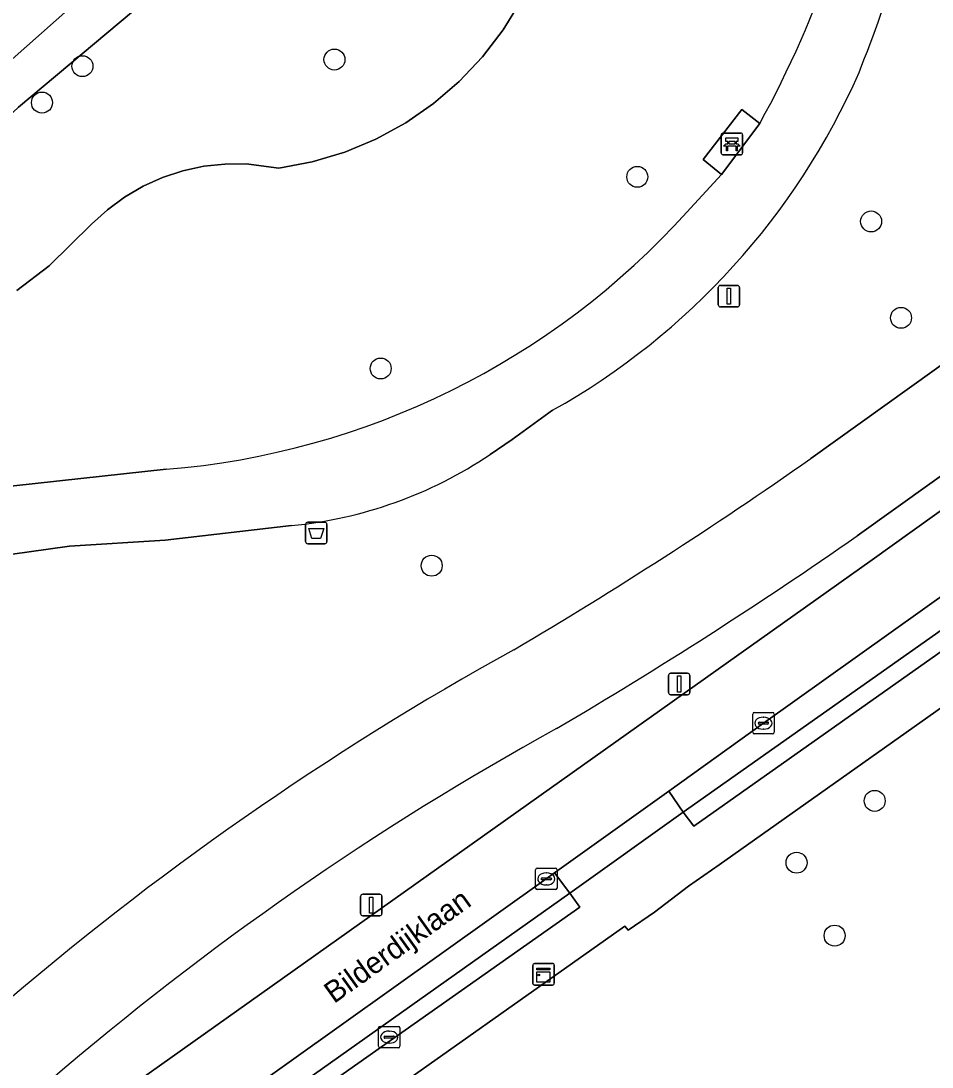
# Model space of a CAD drawing. Extents: x 161347 to 161881, y 382161 to 382804.
# Drawn here: x 161456.75 to 161499.19, y 382680.34 to 382729.09 of the extents above; entities that cross this region are included whole.
import ezdxf

# ---------------------------------------------------------------- set-up
doc = ezdxf.new("R2010")
doc.units = 0
for name, color, linetype in [('IMGEO_Afvalbak', 7, 'Continuous'), ('IMGEO_Bank', 7, 'Continuous'), ('IMGEO_Berm_groen', 7, 'Continuous'), ('IMGEO_Boom', 7, 'Continuous'), ('IMGEO_Erf', 7, 'Continuous'), ('IMGEO_Fietspad_gesloten', 7, 'Continuous'), ('IMGEO_Groenvoorziening', 7, 'Continuous'), ('IMGEO_Kast', 7, 'Continuous'), ('IMGEO_Kolk', 7, 'Continuous'), ('IMGEO_Lichtmast', 7, 'Continuous'), ('IMGEO_Oever', 7, 'Continuous'), ('IMGEO_Openbare_ruimte_label', 7, 'Continuous'), ('IMGEO_Rijbaan_lokaal_open', 7, 'Continuous'), ('IMGEO_Voetpad_gesloten', 7, 'Continuous'), ('IMGEO_Voetpad_open', 7, 'Continuous'), ('IMGEO_Waterloop', 7, 'Continuous')]:
    doc.layers.add(name, color=color, linetype=linetype)

msp = doc.modelspace()

# ---------------------------------------------------------------- linework, layer by layer
at = {"layer": 'IMGEO_Afvalbak'}
for p, q in [((161470.113, 382705.732), (161470.903, 382705.732)), ((161470.903, 382705.732), (161470.113, 382705.732)), ((161470.013, 382704.832), (161470.013, 382705.632)), ((161470.013, 382705.632), (161470.013, 382704.832)), ((161471.003, 382705.632), (161471.003, 382704.832)), ((161471.003, 382704.832), (161471.003, 382705.632)), ((161470.903, 382704.732), (161470.113, 382704.732)), ((161470.113, 382704.732), (161470.903, 382704.732))]:
    msp.add_line(p, q, dxfattribs=at)
msp.add_lwpolyline([(161470.156, 382705.446), (161470.86, 382705.446), (161470.711, 382704.976), (161470.305, 382704.976), (161470.156, 382705.446)], dxfattribs=at)
for centre, start, end in [((161470.113, 382705.632), 90, 180), ((161470.113, 382705.632), 90, 180), ((161470.903, 382705.632), 0, 90), ((161470.903, 382705.632), 360, 90), ((161470.113, 382704.832), 180, 270), ((161470.113, 382704.832), 180, 270), ((161470.903, 382704.832), 270, 0), ((161470.903, 382704.832), 270, 0)]:
    msp.add_arc(centre, 0.1, start, end, dxfattribs=at)
at = {"layer": 'IMGEO_Bank'}
for p, q in [((161489.37, 382722.935), (161489.37, 382723.776)), ((161489.37, 382723.776), (161489.37, 382722.935)), ((161489.445, 382723.86), (161490.286, 382723.86)), ((161490.286, 382723.86), (161489.445, 382723.86)), ((161490.37, 382723.785), (161490.37, 382722.944)), ((161490.37, 382722.944), (161490.37, 382723.785)), ((161489.679, 382723.366), (161489.679, 382723.472)), ((161489.723, 382723.472), (161489.723, 382723.366)), ((161490.011, 382723.478), (161489.729, 382723.478)), ((161489.729, 382723.36), (161490.011, 382723.36)), ((161490.017, 382723.366), (161490.017, 382723.472)), ((161490.061, 382723.472), (161490.061, 382723.366)), ((161490.295, 382722.86), (161489.454, 382722.86)), ((161489.454, 382722.86), (161490.295, 382722.86)), ((161490.067, 382723.258), (161489.674, 382723.258))]:
    msp.add_line(p, q, dxfattribs=at)
for points in [[(161489.617, 382723.258), (161489.475, 382723.258), (161489.587, 382723.36), (161489.673, 382723.36)], [(161489.673, 382723.478), (161489.587, 382723.478), (161489.587, 382723.639), (161490.15, 382723.639), (161490.15, 382723.478), (161490.067, 382723.478)], [(161490.067, 382723.36), (161490.15, 382723.36), (161490.262, 382723.258), (161490.123, 382723.258)], [(161489.667, 382723.251), (161489.667, 382723.044), (161489.624, 382723.044), (161489.624, 382723.251)], [(161490.117, 382723.251), (161490.117, 382723.044), (161490.073, 382723.044), (161490.073, 382723.251)]]:
    msp.add_lwpolyline(points, dxfattribs=at)
for centre, radius, start, end in [((161489.448, 382723.782), 0.0779, 92.4484, 184.2845), ((161489.448, 382723.782), 0.0779, 92.4484, 184.2845), ((161490.292, 382723.782), 0.0779, 2.4484, 94.2845), ((161490.292, 382723.782), 0.0779, 2.4484, 94.2845), ((161489.672, 382723.471), 0.00671, 2.8957, 87.1043), ((161489.672, 382723.367), 0.00671, 272.8957, 357.1043), ((161489.729, 382723.471), 0.00671, 92.8957, 177.1043), ((161489.729, 382723.367), 0.00671, 182.8957, 267.1043), ((161490.011, 382723.471), 0.00671, 2.8957, 87.1043), ((161490.011, 382723.367), 0.00671, 272.8957, 357.1043), ((161490.068, 382723.471), 0.00671, 92.8957, 177.1043), ((161490.068, 382723.367), 0.00671, 182.8957, 267.1043), ((161489.448, 382722.938), 0.0779, 182.4484, 274.2845), ((161489.448, 382722.938), 0.0779, 182.4484, 274.2845), ((161489.617, 382723.251), 0.00671, 2.8957, 87.1043), ((161489.674, 382723.251), 0.00671, 92.8957, 177.1043), ((161490.066, 382723.251), 0.00671, 2.8957, 87.1043), ((161490.123, 382723.251), 0.00671, 92.8957, 177.1043), ((161490.292, 382722.938), 0.0779, 272.4484, 4.2845), ((161490.292, 382722.938), 0.0779, 272.4484, 4.2845)]:
    msp.add_arc(centre, radius, start, end, dxfattribs=at)
at = {"layer": 'IMGEO_Berm_groen'}
for points in [[(161496.406, 382703.987), (161520.561, 382721.294), (161534.16, 382731.042), (161532.366, 382733.661), (161532.246, 382733.831)], [(161519.837, 382722.372), (161495.711, 382705.094)], [(161458.111, 382679.715), (161459.5, 382677.759), (161461.177, 382678.951), (161496.406, 382703.987)]]:
    msp.add_lwpolyline(points, dxfattribs=at)
for points in [[(161537.789, 382727.63), (161537.522, 382728.039), (161536.889, 382728.907), (161530.645, 382724.485), (161516.475, 382714.369), (161503.123, 382704.778), (161491.34, 382696.368), (161486.926, 382693.195), (161487.602, 382692.215)], [(161482.326, 382688.441), (161481.611, 382689.399), (161481.225, 382689.112), (161464.586, 382677.241), (161463.154, 382676.198), (161461.489, 382674.961), (161462.097, 382674.118)]]:
    msp.add_lwpolyline(points, close=True, dxfattribs=at)
for centre, radius, start, end in [((161369.649, 382886.421), 220.842, 300.49014, 304.80775), ((161548.88, 382574.336), 139.082, 118.88221, 130.74015)]:
    msp.add_arc(centre, radius, start, end, dxfattribs=at)
at = {"layer": 'IMGEO_Boom'}
for centre in [(161471.354, 382727.292), (161459.614, 382726.984), (161457.731, 382725.286), (161485.462, 382721.827), (161496.355, 382719.749), (161497.748, 382715.257), (161473.509, 382712.896), (161475.885, 382703.708), (161496.521, 382692.749), (161492.882, 382689.868), (161494.655, 382686.468)]:
    msp.add_circle(centre, 0.489, dxfattribs=at)
at = {"layer": 'IMGEO_Erf'}
msp.add_lwpolyline([(161539.475, 382725.265), (161539.023, 382724.966), (161500, 382697.359), (161489.273, 382689.77), (161487.851, 382688.777), (161486.262, 382687.566), (161485.031, 382686.717), (161484.889, 382686.908), (161471.792, 382677.655), (161467.896, 382674.919)], dxfattribs=at)
at = {"layer": 'IMGEO_Fietspad_gesloten'}
for points in [[(161523.309, 382730.357), (161521.173, 382728.603), (161519.215, 382727.108), (161518.831, 382726.815), (161493.541, 382708.697)], [(161495.711, 382705.094), (161519.837, 382722.372)]]:
    msp.add_lwpolyline(points, dxfattribs=at)
for centre, radius, start, end in [((161374.116, 382878.995), 207.999, 300.50782, 305.04089), ((161369.649, 382886.421), 220.842, 300.49014, 304.80775), ((161548.803, 382574.988), 142.653, 118.97036, 130.86988), ((161548.88, 382574.336), 139.082, 118.88221, 130.74015)]:
    msp.add_arc(centre, radius, start, end, dxfattribs=at)
at = {"layer": 'IMGEO_Groenvoorziening'}
for points in [[(161472.613, 382738.476), (161456.64, 382725.075)], [(161456.559, 382716.525), (161458.069, 382717.676), (161460.04, 382719.626), (161460.777, 382720.295), (161461.579, 382720.884), (161462.439, 382721.385), (161463.347, 382721.794), (161464.292, 382722.106), (161465.265, 382722.317), (161466.254, 382722.425), (161467.249, 382722.43), (161468.77, 382722.233), (161470.321, 382722.525), (161471.833, 382722.977), (161473.29, 382723.585), (161474.675, 382724.342), (161475.974, 382725.239), (161477.171, 382726.267), (161478.255, 382727.415), (161479.212, 382728.67), (161480.034, 382730.018)], [(161480.034, 382730.018), (161479.212, 382728.67), (161478.255, 382727.415), (161477.171, 382726.267), (161475.974, 382725.239), (161474.675, 382724.342), (161473.29, 382723.585), (161471.833, 382722.977), (161470.321, 382722.525), (161468.77, 382722.233), (161467.249, 382722.43), (161466.254, 382722.425), (161465.265, 382722.317), (161464.292, 382722.106), (161463.347, 382721.794), (161462.439, 382721.385), (161461.579, 382720.884), (161460.777, 382720.295), (161460.04, 382719.626), (161458.069, 382717.676), (161456.559, 382716.525)], [(161493.541, 382708.697), (161518.831, 382726.815)], [(161487.776, 382720.188), (161489.381, 382721.932), (161488.535, 382722.639), (161490.336, 382724.963), (161491.169, 382724.314)], [(161481.517, 382710.948), (161479.63, 382709.589), (161478.603, 382708.888)], [(161453.419, 382707.1), (161463.511, 382708.198)], [(161469.355, 382705.575), (161463.467, 382704.901), (161459.017, 382704.615), (161452.58, 382703.712), (161450.029, 382703.228), (161448.055, 382702.486), (161447.132, 382702.068), (161445.435, 382701.104), (161442.413, 382699.254), (161439.915, 382696.828), (161438.465, 382695.203), (161433.965, 382689.139), (161439.833, 382684.963), (161443.031, 382682.767), (161445.834, 382680.886)]]:
    msp.add_lwpolyline(points, dxfattribs=at)
for points in [[(161537.789, 382727.63), (161487.602, 382692.215), (161488.093, 382691.571), (161538.259, 382727.022)], [(161482.783, 382687.789), (161482.326, 382688.441), (161462.097, 382674.118), (161462.528, 382673.52)]]:
    msp.add_lwpolyline(points, close=True, dxfattribs=at)
for centre, radius, start, end in [((161447.83, 382748.107), 49.44, 331.2337, 351.2119), ((161426.836, 382754.189), 74.236, 338.25891, 347.08272), ((161465.125, 382740.155), 33.492, 299.3027, 336.2968), ((161460.556, 382744.728), 36.649, 274.6255, 317.965), ((161467.429, 382725.517), 20.034, 275.5179, 303.9012), ((161374.116, 382878.995), 207.999, 300.50782, 305.04089), ((161548.803, 382574.988), 142.653, 118.97036, 130.86988)]:
    msp.add_arc(centre, radius, start, end, dxfattribs=at)
at = {"layer": 'IMGEO_Kast'}
for p, q in [((161480.595, 382684.243), (161480.595, 382685.084)), ((161480.595, 382685.084), (161480.595, 382684.243)), ((161480.67, 382685.168), (161481.511, 382685.168)), ((161481.511, 382685.168), (161480.67, 382685.168)), ((161481.595, 382685.093), (161481.595, 382684.252)), ((161481.595, 382684.252), (161481.595, 382685.093)), ((161481.52, 382684.168), (161480.679, 382684.168)), ((161480.679, 382684.168), (161481.52, 382684.168))]:
    msp.add_line(p, q, dxfattribs=at)
for points in [[(161480.79, 382684.958), (161481.39, 382684.958), (161481.39, 382684.873), (161480.79, 382684.873), (161480.79, 382684.958)], [(161480.79, 382684.783), (161481.39, 382684.783), (161481.39, 382684.294), (161480.79, 382684.294), (161480.79, 382684.783)]]:
    msp.add_lwpolyline(points, dxfattribs=at)
msp.add_circle((161480.874, 382684.632), 0.0377, dxfattribs=at)
for centre, start, end in [((161480.673, 382685.09), 92.4484, 184.2845), ((161480.673, 382685.09), 92.4484, 184.2845), ((161481.517, 382685.09), 2.4484, 94.2845), ((161481.517, 382685.09), 2.4484, 94.2845), ((161480.673, 382684.246), 182.4484, 274.2845), ((161480.673, 382684.246), 182.4484, 274.2845), ((161481.517, 382684.246), 272.4484, 4.2845), ((161481.517, 382684.246), 272.4484, 4.2845)]:
    msp.add_arc(centre, 0.0779, start, end, dxfattribs=at)
at = {"layer": 'IMGEO_Kolk'}
for p, q in [((161490.839, 382695.942), (161490.839, 382696.794)), ((161490.914, 382696.868), (161491.766, 382696.868)), ((161491.327, 382696.648), (161491.352, 382696.648)), ((161491.84, 382696.794), (161491.84, 382695.942)), ((161491.098, 382696.362), (161491.098, 382696.374)), ((161491.536, 382696.325), (161491.138, 382696.325)), ((161491.141, 382696.411), (161491.539, 382696.411)), ((161491.35, 382696.088), (161491.325, 382696.088)), ((161491.582, 382696.374), (161491.582, 382696.362)), ((161491.766, 382695.868), (161490.914, 382695.868)), ((161480.724, 382688.686), (161480.724, 382689.538)), ((161480.799, 382689.612), (161481.651, 382689.612)), ((161481.026, 382689.155), (161481.424, 382689.155)), ((161481.212, 382689.392), (161481.237, 382689.392)), ((161481.725, 382689.538), (161481.725, 382688.686)), ((161480.983, 382689.106), (161480.983, 382689.118)), ((161481.421, 382689.069), (161481.023, 382689.069)), ((161481.235, 382688.832), (161481.21, 382688.832)), ((161481.467, 382689.118), (161481.467, 382689.106)), ((161481.651, 382688.612), (161480.799, 382688.612)), ((161473.406, 382681.313), (161473.406, 382682.165)), ((161473.481, 382682.239), (161474.333, 382682.239)), ((161473.894, 382682.019), (161473.919, 382682.019)), ((161474.407, 382682.165), (161474.407, 382681.313)), ((161473.665, 382681.733), (161473.665, 382681.745)), ((161474.103, 382681.696), (161473.705, 382681.696)), ((161473.708, 382681.782), (161474.106, 382681.782)), ((161473.917, 382681.459), (161473.892, 382681.459)), ((161474.149, 382681.745), (161474.149, 382681.733)), ((161474.333, 382681.239), (161473.481, 382681.239))]:
    msp.add_line(p, q, dxfattribs=at)
for points in [[(161490.839, 382695.942), (161490.839, 382696.794)], [(161490.914, 382696.868), (161491.766, 382696.868)], [(161491.84, 382696.794), (161491.84, 382695.942)], [(161491.766, 382695.868), (161490.914, 382695.868)], [(161480.724, 382688.686), (161480.724, 382689.538)], [(161480.799, 382689.612), (161481.651, 382689.612)], [(161481.725, 382689.538), (161481.725, 382688.686)], [(161481.651, 382688.612), (161480.799, 382688.612)], [(161473.406, 382681.313), (161473.406, 382682.165)], [(161473.481, 382682.239), (161474.333, 382682.239)], [(161474.407, 382682.165), (161474.407, 382681.313)], [(161474.333, 382681.239), (161473.481, 382681.239)]]:
    msp.add_lwpolyline(points, dxfattribs=at)
for centre, radius, start, end in [((161490.916, 382696.792), 0.0765, 91.552, 178.448), ((161490.916, 382696.792), 0.0765, 91.552, 178.448), ((161491.764, 382696.792), 0.0765, 1.552, 88.448), ((161491.764, 382696.792), 0.0765, 1.552, 88.448), ((161491.138, 382696.371), 0.0403, 85.8775, 175.7526), ((161491.135, 382696.361), 0.0366, 178.938, 274.7102), ((161491.539, 382696.368), 0.043, 264.8664, 352.4533), ((161491.543, 382696.373), 0.0386, 1.7309, 96.639), ((161490.916, 382695.944), 0.0765, 181.552, 268.448), ((161490.916, 382695.944), 0.0765, 181.552, 268.448), ((161491.764, 382695.944), 0.0765, 271.552, 358.448), ((161491.764, 382695.944), 0.0765, 271.552, 358.448), ((161480.801, 382689.536), 0.0765, 91.552, 178.448), ((161480.801, 382689.536), 0.0765, 91.552, 178.448), ((161481.023, 382689.115), 0.0403, 85.8775, 175.7526), ((161481.428, 382689.117), 0.0386, 1.7309, 96.639), ((161481.649, 382689.536), 0.0765, 1.552, 88.448), ((161481.649, 382689.536), 0.0765, 1.552, 88.448), ((161480.801, 382688.688), 0.0765, 181.552, 268.448), ((161480.801, 382688.688), 0.0765, 181.552, 268.448), ((161481.02, 382689.105), 0.0366, 178.938, 274.7102), ((161481.424, 382689.112), 0.043, 264.8664, 352.4533), ((161481.649, 382688.688), 0.0765, 271.552, 358.448), ((161481.649, 382688.688), 0.0765, 271.552, 358.448), ((161473.483, 382682.163), 0.0765, 91.552, 178.448), ((161473.483, 382682.163), 0.0765, 91.552, 178.448), ((161474.331, 382682.163), 0.0765, 1.552, 88.448), ((161474.331, 382682.163), 0.0765, 1.552, 88.448), ((161473.705, 382681.742), 0.0403, 85.8775, 175.7526), ((161473.702, 382681.732), 0.0366, 178.938, 274.7102), ((161474.106, 382681.739), 0.043, 264.8664, 352.4533), ((161474.11, 382681.744), 0.0386, 1.7309, 96.639), ((161473.483, 382681.315), 0.0765, 181.552, 268.448), ((161473.483, 382681.315), 0.0765, 181.552, 268.448), ((161474.331, 382681.315), 0.0765, 271.552, 358.448), ((161474.331, 382681.315), 0.0765, 271.552, 358.448)]:
    msp.add_arc(centre, radius, start, end, dxfattribs=at)
for centre, major_axis, ratio, start_param, end_param in [((161491.326, 382696.368), (-0.387, 0.002), 0.722429, 4.712389, 7.853982), ((161491.351, 382696.368), (-0.39, 0.002), 0.717154, 1.570796, 4.712389), ((161481.211, 382689.112), (-0.387, 0.002), 0.722429, 4.712389, 7.853982), ((161481.236, 382689.112), (-0.39, 0.002), 0.717154, 1.570796, 4.712389), ((161473.893, 382681.739), (-0.387, 0.002), 0.722429, 4.712389, 7.853982), ((161473.918, 382681.739), (-0.39, 0.002), 0.717154, 1.570796, 4.712389)]:
    msp.add_ellipse(centre, major_axis=major_axis, ratio=ratio, start_param=start_param, end_param=end_param, dxfattribs=at)
at = {"layer": 'IMGEO_Lichtmast'}
for p, q in [((161489.236, 382715.868), (161489.236, 382716.668)), ((161489.236, 382716.668), (161489.236, 382715.868)), ((161489.336, 382716.768), (161490.126, 382716.768)), ((161490.126, 382716.768), (161489.336, 382716.768)), ((161490.226, 382716.668), (161490.226, 382715.868)), ((161490.226, 382715.868), (161490.226, 382716.668)), ((161490.126, 382715.768), (161489.336, 382715.768)), ((161489.336, 382715.768), (161490.126, 382715.768)), ((161486.917, 382697.796), (161486.917, 382698.596)), ((161486.917, 382698.596), (161486.917, 382697.796)), ((161487.017, 382698.696), (161487.807, 382698.696)), ((161487.807, 382698.696), (161487.017, 382698.696)), ((161487.907, 382698.596), (161487.907, 382697.796)), ((161487.907, 382697.796), (161487.907, 382698.596)), ((161487.807, 382697.696), (161487.017, 382697.696)), ((161487.017, 382697.696), (161487.807, 382697.696)), ((161472.575, 382687.493), (161472.575, 382688.293)), ((161472.575, 382688.293), (161472.575, 382687.493)), ((161472.675, 382688.393), (161473.465, 382688.393)), ((161473.465, 382688.393), (161472.675, 382688.393)), ((161473.565, 382688.293), (161473.565, 382687.493)), ((161473.565, 382687.493), (161473.565, 382688.293)), ((161473.465, 382687.393), (161472.675, 382687.393)), ((161472.675, 382687.393), (161473.465, 382687.393))]:
    msp.add_line(p, q, dxfattribs=at)
for points in [[(161489.656, 382716.643), (161489.806, 382716.643), (161489.806, 382715.893), (161489.656, 382715.893), (161489.656, 382716.643)], [(161487.337, 382698.571), (161487.487, 382698.571), (161487.487, 382697.821), (161487.337, 382697.821), (161487.337, 382698.571)], [(161472.995, 382688.268), (161473.145, 382688.268), (161473.145, 382687.518), (161472.995, 382687.518), (161472.995, 382688.268)]]:
    msp.add_lwpolyline(points, dxfattribs=at)
for centre, start, end in [((161489.336, 382716.668), 90, 180), ((161489.336, 382716.668), 90, 180), ((161490.126, 382716.668), 0, 90), ((161490.126, 382716.668), 360, 90), ((161489.336, 382715.868), 180, 270), ((161489.336, 382715.868), 180, 270), ((161490.126, 382715.868), 270, 0), ((161490.126, 382715.868), 270, 0), ((161487.017, 382698.596), 90, 180), ((161487.017, 382698.596), 90, 180), ((161487.807, 382698.596), 0, 90), ((161487.807, 382698.596), 360, 90), ((161487.017, 382697.796), 180, 270), ((161487.017, 382697.796), 180, 270), ((161487.807, 382697.796), 270, 0), ((161487.807, 382697.796), 270, 0), ((161472.675, 382688.293), 90, 180), ((161472.675, 382688.293), 90, 180), ((161473.465, 382688.293), 0, 90), ((161473.465, 382688.293), 360, 90), ((161472.675, 382687.493), 180, 270), ((161472.675, 382687.493), 180, 270), ((161473.465, 382687.493), 270, 0), ((161473.465, 382687.493), 270, 0)]:
    msp.add_arc(centre, 0.1, start, end, dxfattribs=at)
at = {"layer": 'IMGEO_Oever'}
msp.add_lwpolyline([(161464.939, 382734.95), (161453.053, 382724.402), (161448.458, 382721.01), (161442.745, 382716.146), (161436.564, 382709.603), (161429.314, 382701.3), (161425.664, 382695.57), (161431.282, 382691.759), (161435.082, 382698.355), (161437.418, 382702.795), (161441.4, 382709.277), (161443.448, 382711.917), (161448.031, 382717), (161456.64, 382725.075), (161472.613, 382738.476)], dxfattribs=at)
at = {"layer": 'IMGEO_Rijbaan_lokaal_open'}
msp.add_lwpolyline([(161546.949, 382740.061), (161546.454, 382739.715), (161537.494, 382733.394), (161534.16, 382731.042), (161520.561, 382721.294), (161496.406, 382703.987), (161461.177, 382678.951), (161463.154, 382676.198), (161464.586, 382677.241), (161481.225, 382689.112), (161481.611, 382689.399), (161486.926, 382693.195), (161491.34, 382696.368), (161503.123, 382704.778), (161516.475, 382714.369)], dxfattribs=at)
at = {"layer": 'IMGEO_Voetpad_gesloten'}
msp.add_lwpolyline([(161491.169, 382724.314), (161490.336, 382724.963), (161488.535, 382722.639), (161489.381, 382721.932)], close=True, dxfattribs=at)
for points in [[(161491.169, 382724.314), (161489.381, 382721.932), (161487.776, 382720.188)], [(161478.603, 382708.888), (161479.63, 382709.589), (161481.517, 382710.948)], [(161463.511, 382708.198), (161453.419, 382707.1)], [(161435.719, 382696.708), (161431.495, 382690.897), (161433.965, 382689.139), (161438.465, 382695.203), (161439.915, 382696.828), (161442.413, 382699.254), (161445.435, 382701.104), (161447.132, 382702.068), (161448.055, 382702.486), (161450.029, 382703.228), (161452.58, 382703.712), (161459.017, 382704.615), (161463.467, 382704.901), (161469.355, 382705.575)]]:
    msp.add_lwpolyline(points, dxfattribs=at)
for centre, radius, start, end in [((161447.83, 382748.107), 49.44, 331.2337, 351.2119), ((161426.836, 382754.189), 74.236, 338.25891, 347.08272), ((161465.125, 382740.155), 33.492, 299.3027, 336.2968), ((161460.556, 382744.728), 36.649, 274.6255, 317.965), ((161467.429, 382725.517), 20.034, 275.5179, 303.9012)]:
    msp.add_arc(centre, radius, start, end, dxfattribs=at)
at = {"layer": 'IMGEO_Voetpad_open'}
for points in [[(161549.126, 382737.515), (161550.024, 382736.474), (161550.547, 382735.868), (161544.286, 382731.374), (161543.803, 382732.012), (161543.561, 382732.331), (161537.522, 382728.039), (161537.789, 382727.63), (161538.259, 382727.022), (161488.093, 382691.571), (161487.602, 382692.215), (161482.326, 382688.441), (161482.783, 382687.789), (161462.528, 382673.52), (161462.097, 382674.118), (161461.489, 382674.961), (161461.142, 382674.732)], [(161467.896, 382674.919), (161471.792, 382677.655), (161484.889, 382686.908), (161485.031, 382686.717), (161486.262, 382687.566), (161487.851, 382688.777), (161489.273, 382689.77), (161500, 382697.359), (161539.023, 382724.966), (161539.475, 382725.265)]]:
    msp.add_lwpolyline(points, dxfattribs=at)
msp.add_lwpolyline([(161486.926, 382693.195), (161481.611, 382689.399), (161482.326, 382688.441), (161487.602, 382692.215)], close=True, dxfattribs=at)
at = {"layer": 'IMGEO_Waterloop'}
msp.add_lwpolyline([(161414.137, 382638.4), (161414.462, 382642.019), (161414.507, 382642.881), (161415.108, 382654.253), (161416.032, 382662.071), (161416.828, 382667.41), (161418.679, 382677.698), (161420.108, 382683.14), (161420.288, 382683.559), (161421.366, 382686.066), (161425.204, 382691.597), (161425.605, 382694.979), (161425.664, 382695.57), (161429.314, 382701.3), (161436.564, 382709.603), (161442.745, 382716.146), (161448.458, 382721.01), (161453.053, 382724.402), (161464.939, 382734.95)], dxfattribs=at)

# ---------------------------------------------------------------- texts
at = {"layer": 'IMGEO_Openbare_ruimte_label'}
msp.add_text('Bilderdijklaan', height=1, rotation=35.5976, dxfattribs=at).set_placement((161471.336, 382683.276))

doc.saveas('drawing.dxf')
